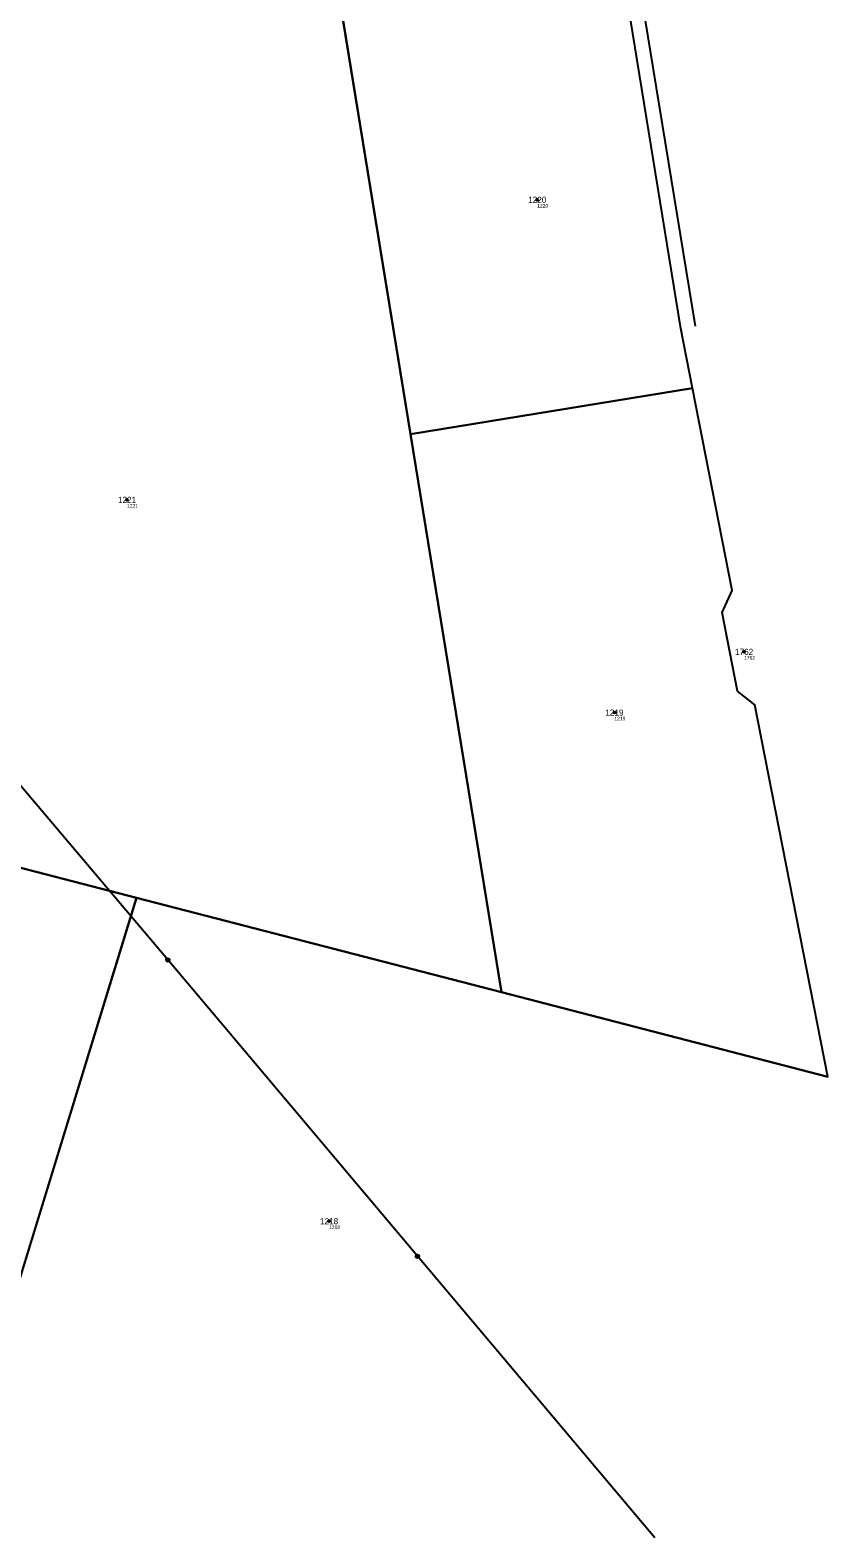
# Model space of a CAD drawing. Extents: x -781091 to -780384, y -1093010 to -1092030.
# Drawn here: x -780727 to -780504.9, y -1093010.1 to -1092590.4 of the extents above; entities that cross this region are included whole.
import ezdxf

# ---------------------------------------------------------------- set-up
doc = ezdxf.new("R2010")
doc.units = 0
for name, color, linetype in [('Vrstva 1', 7, 'Continuous'), ('Vrstva 2', 7, 'Continuous'), ('Vrstva 50', 7, 'Continuous'), ('Vrstva 51', 7, 'Continuous'), ('Vrstva 6', 7, 'Continuous')]:
    doc.layers.add(name, color=color, linetype=linetype)

msp = doc.modelspace()

# ---------------------------------------------------------------- linework, layer by layer
at = {"layer": 'Vrstva 1'}
for p, q in [((-780643.35, -1092566.12), (-780621.09, -1092702.81)), ((-780558.33, -1092571.84), (-780541.89, -1092672.78)), ((-780542.57, -1092690.03), (-780621.09, -1092702.81)), ((-780621.09, -1092702.81), (-780595.78, -1092858.19)), ((-780732.85, -1092822.7), (-780697.38, -1092831.88)), ((-780697.38, -1092831.88), (-780737.57, -1092962.77)), ((-780595.78, -1092858.19), (-780697.38, -1092831.88)), ((-780504.92, -1092881.71), (-780595.78, -1092858.19))]:
    msp.add_line(p, q, dxfattribs=at)
for points in [[(-780542.57, -1092690.03), (-780545.84, -1092673.37), (-780565.63, -1092551.86), (-780566.65, -1092548.58)], [(-780504.92, -1092881.71), (-780525.26, -1092778.18), (-780530.08, -1092774.38), (-780534.35, -1092752.45), (-780531.51, -1092746.36), (-780542.57, -1092690.03)]]:
    msp.add_lwpolyline(points, dxfattribs=at)
at = {"layer": 'Vrstva 50'}
for centre in [(-780585.84, -1092637.56994), (-780700.03, -1092721.09994), (-780528.25, -1092763.40994), (-780564.35, -1092780.31994), (-780643.78, -1092921.90994)]:
    msp.add_circle(centre, 0.25, dxfattribs=at)
at = {"layer": 'Vrstva 51'}
for points in [[(-780643.35, -1092566.12), (-780621.09, -1092702.81), (-780542.57, -1092690.03), (-780545.84, -1092673.37), (-780565.63, -1092551.86), (-780566.65, -1092548.58), (-780588.7, -1092556.87), (-780619.47, -1092562.21)], [(-780765.06, -1092581.92), (-780774.6, -1092648.53), (-780795.32, -1092784.28), (-780798.44, -1092805.72), (-780769.96, -1092813.09), (-780753, -1092817.48), (-780732.85, -1092822.7), (-780697.38, -1092831.88), (-780595.78, -1092858.19), (-780621.09, -1092702.81), (-780643.35, -1092566.12), (-780644.91, -1092566.38), (-780712.05, -1092575.19)], [(-780525.26, -1092778.18), (-780530.08, -1092774.38), (-780534.35, -1092752.45), (-780531.51, -1092746.36), (-780542.57, -1092690.03), (-780621.09, -1092702.81), (-780595.78, -1092858.19), (-780504.92, -1092881.71)], [(-780750.21, -1092959.6), (-780737.57, -1092962.77), (-780697.38, -1092831.88), (-780732.85, -1092822.7), (-780783.81, -1092988.64), (-780760.45, -1092996.86), (-780756.27, -1092981.67)]]:
    msp.add_lwpolyline(points, close=True, dxfattribs=at)
at = {"layer": 'Vrstva 6'}
for p, q in [((-780688.65, -1092849.19), (-780759.93, -1092764.96)), ((-780619.17, -1092931.67), (-780688.65, -1092849.19)), ((-780553.11, -1093010.05), (-780619.17, -1092931.67))]:
    msp.add_line(p, q, dxfattribs=at)
for centre, radius in [((-780688.65343, -1092849.18988), 0.5), ((-780688.65343, -1092849.18988), 0.4), ((-780688.65343, -1092849.18988), 0.3), ((-780688.65343, -1092849.18988), 0.2), ((-780688.65343, -1092849.18988), 0.1), ((-780619.17343, -1092931.66988), 0.5), ((-780619.17343, -1092931.66988), 0.4), ((-780619.17343, -1092931.66988), 0.3), ((-780619.17343, -1092931.66988), 0.2), ((-780619.17343, -1092931.66988), 0.1)]:
    msp.add_circle(centre, radius, dxfattribs=at)

# ---------------------------------------------------------------- texts
at = {"layer": 'Vrstva 2'}
for s, p in [('1220', (-780588.347, -1092638.42)), ('1221', (-780702.537, -1092721.95)), ('1762', (-780530.757, -1092764.26)), ('1219', (-780566.857, -1092781.17)), ('1218', (-780646.287, -1092922.76))]:
    msp.add_text(s, height=1.699998, dxfattribs=at).set_placement(p)
at = {"layer": 'Vrstva 50'}
for s, p in [('1220', (-780585.84, -1092639.726)), ('1221', (-780700.03, -1092723.256)), ('1762', (-780528.25, -1092765.566)), ('1219', (-780564.35, -1092782.476)), ('1218', (-780643.78, -1092924.066))]:
    msp.add_text(s, height=0.999996, dxfattribs=at).set_placement(p)

doc.saveas('drawing.dxf')
